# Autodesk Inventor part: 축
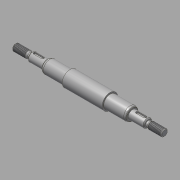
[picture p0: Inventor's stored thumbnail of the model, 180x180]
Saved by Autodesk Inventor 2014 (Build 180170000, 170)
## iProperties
Created: 2015-11
Part Number: 축
Material: 강철, 연강
Document SubType Name: Modeling
Designer: mduedu
Density: 1 g/cm^3
Appearance: Steel
Author: mduedu
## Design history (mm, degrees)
sketch "스케치1"
  geometry: L1 (-86, 0)-(86, 0); L2 (-86, 0)-(-86, 4); L3 (-86, 4)-(-70.732, 4); L4 (-70.732, 4)-(-69, 3); L5 (-69, 3)-(-67, 3); L6 (-67, 3)-(-67, 5); L7 (-67, 5)-(-49, 5); L8 (-49, 5)-(-49, 6.55); L9 (-47.355, 7.5)-(-23, 7.5); L10 (-23, 7.5)-(-23, 9); L11 (0, 0)-(0, 9); L12 (86, 4)-(70.732, 4); L13 (70.732, 4)-(69, 3); L14 (69, 3)-(67, 3); L15 (67, 3)-(67, 5); L16 (67, 5)-(49, 5); L17 (23, 7.5)-(23, 9); L18 (86, 0)-(86, 4); L19 (-23, 9)-(23, 9); L20 (-49, 6.55)-(-47.355, 7.5); L21 (47.355, 7.5)-(23, 7.5); L22 (49, 6.55)-(47.355, 7.5); L23 (49, 5)-(49, 6.55); 1 further point
  constraints: 46 end point, 10 symmetric about line, 6 perpendicular, 5 parallel, 2 midpoint, 1 coincident, 1 horizontal
  dimensions: "d0" = 172 distance of L1.start L1.end (derived); "d1" = 8 diameter of L3 L1; "d2" = 30 deg angle of L4 L5; "d3" = 6 diameter of L5 L1; "d4" = 10 diameter of L7 L1; "d5" = 15 diameter of L9 L1; "d6" = 18 diameter of L19 L1; "d8" = 18 distance of L6.end L7.end; "d9" = 46 distance of L10.end L17.end; "d10" = 2 distance of L4.end L5.end; "d11" = 17 distance from line of L4.end L2; "d16" = 13.1 diameter of L8.end L1; "d17" = 30 deg angle of L20 L9; "d18" = 26 distance between parallel lines of L10 L8
revolve "회전1" sketch "스케치1" stored, may be unused: angle "d12" = 90 deg
chamfer "모따기1" distance "d13" = 1; stored, may be unused: second distance "d14" = 2, angle "d15" = 45 deg
fillet "모깎기1" dims "d19" = 4, "d20" = 0.5
node "작업 평면1"
sketch "스케치2" dims "d23" = 12
  geometry: L1 (-5.5, 1.5)-(3.5, 1.5); L2 (3.5, 1.5)-(3.5, -1.5); L3 (3.5, -1.5)-(-5.5, -1.5); L4 (-5.5, -1.5)-(-5.5, 1.5); L5 (-9, -4)-(-9, 4) reference; 3 further points
  constraints: 8 end point, 2 midpoint, 2 parallel, 2 vertical alignment, 1 horizontal, 1 perpendicular, 4 other
  dimensions: "d21" = 3 distance between parallel lines of L3 L1; "d24" = 2 dimension on L5
extrude "돌출1" cut sketch "스케치2" distance "d25" = 1.8; taper "d26" = 0 deg
feature "스레드1" dims "d27" = 10, "d28" = 0
feature "스레드2" dims "d29" = 10, "d30" = 0
chamfer "모따기2" distance "d31" = 1; stored, may be unused: second distance "d32" = 2, angle "d33" = 45 deg
fillet "모깎기2" dims "d34" = 0.3
node "솔리드1"
mirror "대칭1"
